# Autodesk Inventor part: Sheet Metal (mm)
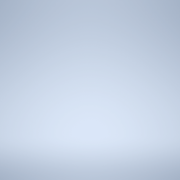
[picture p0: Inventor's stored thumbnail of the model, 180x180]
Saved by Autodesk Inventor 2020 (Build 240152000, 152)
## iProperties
Created: 2019-02
Part Number: Sheet Metal (mm)
Material: Ogólny
Document SubType Name: Konstrukcja blachowa
Density: 1 g/cm^3
Sheet Metal Rule: Domyślny_mm
Appearance: Domyślna
Catalog Web Link: www.expertbooks.pl
Designer: F.Stasiak
Manager: www.cadconsulting.pl
Company: Fabian Stasiak CAD Consulting
Subject: Zbiór ćwiczeń. Autodesk Inventor 2020. Kurs Professional
Author: F.Stasiak
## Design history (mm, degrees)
other parameters: "Grubość" = 0.5 (derived), "WspółczynnikK" = 4.4, "PromieńGięcia" = 0.5 (= Grubość), "SzerokośćGięciaPodcięcia" = 0.5 (= Grubość), "GłębokośćGięciaPodcięcia" = 0.25 (= 0.5 x Grubość), "RozmiarPodcięciaNarożnika" = 2 (= 4 x Grubość), "OdstępPołączenia" = 0.01, "MinimalnaPozostałość" = 1 (= 2 x Grubość), "PromieńPrzejścia" = 0.5 (= PromieńGięcia), "Rozmiar_promienia_Jacobiego" = 0.5 (= PromieńGięcia), "Wielk_odstępu" = 0.5 (= Grubość)
